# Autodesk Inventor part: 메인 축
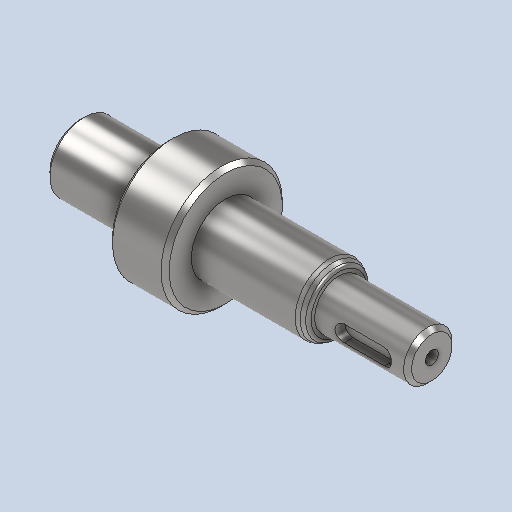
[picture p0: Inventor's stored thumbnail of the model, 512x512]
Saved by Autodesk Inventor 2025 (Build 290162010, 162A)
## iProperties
Created: 2024-07
Part Number: 메인 축
Material: 강철, 연강
Document SubType Name: Modeling
Designer: 계정
Density: 7.86 g/cm^3
Appearance: 기본값
Author: jhkim
Revision Number: 1
Sending System: Autodesk Inventor 2025
Preprocessor: ST-DEVELOPER v20
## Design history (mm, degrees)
feature "솔리드1"
node "솔리드2"
